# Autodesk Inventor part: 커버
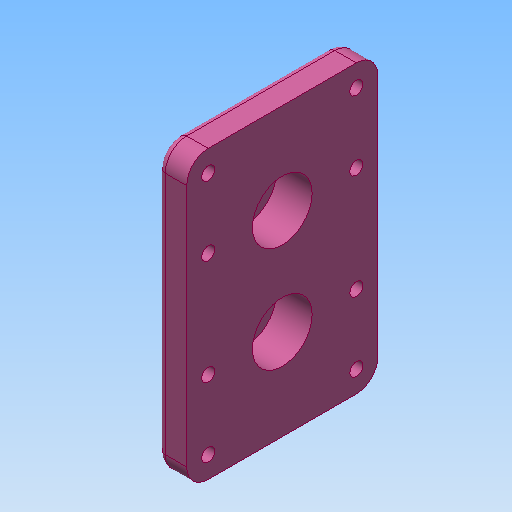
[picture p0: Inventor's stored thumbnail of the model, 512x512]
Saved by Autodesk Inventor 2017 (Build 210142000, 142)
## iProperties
Created: 2019-03
Part Number: 커버
Material: 알루미늄 6061
Document SubType Name: Modeling
Designer: mduedu
Density: 1 g/cm^3
Appearance: 분홍색
Author: mduedu
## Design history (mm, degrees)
sketch "스케치1"
  geometry: L1 (-60, 40)-(60, 40); L2 (60, 40)-(60, -40); L3 (60, -40)-(-60, -40); L4 (-60, -40)-(-60, 40); L5 (-60, 40)-(60, -40); L6 (60, 40)-(-60, -40); 1 further point
  constraints: 12 end point, 2 midpoint, 2 parallel, 1 horizontal, 1 perpendicular
  dimensions: "d59" = 120 distance of L2.end L3.end; "d60" = 80 distance of L1.end L2.end
extrude "돌출1" new body sketch "스케치1" distance "d4" = 12; taper "d5" = 0 deg
sketch "스케치2"
  geometry: L1 (-20, -22)-(20, -22); L2 (20, -22)-(20, 22); L3 (20, 22)-(-20, 22); L4 (-20, 22)-(-20, -22); L5 (-20, -22)-(20, 22); L6 (20, -22)-(-20, 22); 3 further points
  constraints: 12 end point, 4 midpoint, 2 horizontal alignment, 2 parallel, 1 horizontal, 1 perpendicular, 4 other
  dimensions: "d6" = 40 distance between parallel lines of L2 L4; "d8" = 44 distance between parallel lines of L1 L3
extrude "돌출2" join sketch "스케치2" distance "d9" = 10; taper "d10" = 0 deg
fillet "모깎기1" dims "d11" = 9
fillet "모깎기2" dims "d12" = 3
sketch "스케치3"
  geometry: L1 (-31, -60)-(31, -60) reference; L2 (-40, 51)-(-40, -51) reference; L3 (31, 60)-(-31, 60) reference; L4 (40, -51)-(40, 51) reference; L5 (-17, -22)-(-17, 22) reference; L6 (17, 22)-(17, -22) reference; L7 (-31, 51)-(31, 51); L8 (31, 51)-(31, -51); L9 (31, -51)-(-31, -51); L10 (-31, -51)-(-31, 51); A1 r 9 centre (31, -51) between (31, -60) and (40, -51) reference; A2 r 9 centre (-31, -51) between (-40, -51) and (-31, -60) reference; A3 r 9 centre (-31, 51) between (-31, 60) and (-40, 51) reference; A4 r 9 centre (31, 51) between (40, 51) and (31, 60) reference; A5 r 17 centre (0, -22) between (-17, -22) and (17, -22) reference; A6 r 17 centre (0, 22) between (17, 22) and (-17, 22) reference; 9 further points
  constraints: 8 end point, 4 coincident, 4 horizontal alignment, 4 point on line, 2 parallel, 1 horizontal, 1 perpendicular
hole "구멍2" sketch "스케치3" at (-31, 51), (31, 51), (31, -51), (-31, -51), (-31, 22), (-31, -22), (31, 22), (31, -22) diameter "d28" = 5.5; stored, may be unused: countersink angle "d32" = 90 deg, drill point angle "d34" = 118 deg; dims "d29" = 6, "d30" = 4, "d31" = 2, "d33" = 8
sketch "스케치9"
  geometry: L1 (40, -51)-(40, 51) reference; L2 (31, 60)-(-31, 60) reference; L3 (-40, 51)-(-40, -51) reference; L4 (-31, -60)-(31, -60) reference; L5 (23, -22)-(23, 22) reference; L6 (-23, 22)-(-23, -22) reference; C1 r 2.75 at (31, 22) reference; C2 r 2.75 at (-31, 22) reference; C3 r 2.75 at (31, -51) reference; C4 r 2.75 at (-31, 51) reference; C5 r 2.75 at (31, 51) reference; C6 r 2.75 at (-31, -51) reference; C7 r 2.75 at (-31, -22) reference; C8 r 2.75 at (31, -22) reference; A1 r 9 centre (31, -51) between (31, -60) and (40, -51) reference; A2 r 9 centre (31, 51) between (40, 51) and (31, 60) reference; A3 r 9 centre (-31, 51) between (-31, 60) and (-40, 51) reference; A4 r 9 centre (-31, -51) between (-40, -51) and (-31, -60) reference; A5 r 23 centre (0, -22) between (-23, -22) and (23, -22) reference; A6 r 23 centre (0, 22) between (23, 22) and (-23, 22) reference; 9 further points
  constraints: 8 coincident
hole "구멍4" sketch "스케치9" at (-31, 51), (31, 51), (31, 22), (-31, 22), (-31, -22), (31, -22), (31, -51), (-31, -51) diameter "d69" = 11; stored, may be unused: countersink angle "d73" = 90 deg, drill point angle "d75" = 0 deg; dims "d70" = 6, "d71" = 4, "d72" = 2, "d74" = 5.4
fillet "모깎기3" dims "d68" = 3
sketch "스케치6"
  geometry: C1 r 12.5 at (0, 22); 1 further point
  constraints: 1 centre point, 1 vertical alignment
  dimensions: "d43" = 25 diameter of C1; "d45" = 22 distance of C1.centre point (0, 0)
extrude "돌출5" cut sketch "스케치6" distance "d47" = 15; taper "d48" = 0 deg
node "솔리드1"
mirror "대칭1"
node "투영된 루프2"
node "투영된 루프3"
node "투영된 루프4"
